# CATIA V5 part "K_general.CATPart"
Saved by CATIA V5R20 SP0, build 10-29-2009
Part number: general
Publications: "plan_ref"
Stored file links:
  G:\Khaled_CFAO_2011\ST2M\ST2M_GR2\echouteau\Khaled\CAD_ThinkMotion\K_general.CATPart

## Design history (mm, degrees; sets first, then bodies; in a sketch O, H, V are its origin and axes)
Body1 (main body)
  Plane1 "plan_ref": type Offset, RefPlane xy-plane, Offset 0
